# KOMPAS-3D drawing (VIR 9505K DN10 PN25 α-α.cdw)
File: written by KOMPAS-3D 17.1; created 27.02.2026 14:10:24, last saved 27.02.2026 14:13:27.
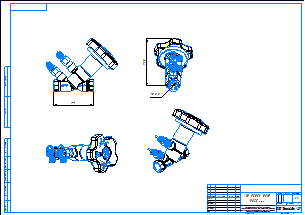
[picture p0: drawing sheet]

Sheet 1: A2, landscape

Title block, sheet 1: name: VIR 9505K DN10 / PN25 р-р; material: Внимание! Данный продукт является объектом авторского права ООО «Торговый Дом АДЛ». / Запрещается изменение, копирование, распространение / (в том числе путем копирования на другие сайты и ресурсы в Интернете) / или любое иное использование информации и объектов без предварительного / согласия правообладателя (ООО «Торговый Дом АДЛ»).; sheets: 1; organisation: ООО "Торговый дом АДЛ"; sheet format: A2

Views: Вид 1, Спереди, Проекционный вид 2, Проекционный вид 3, Вид 4, Изометрия
Referenced files in C:\Users\mipv\Desktop\VIR 9505K STP формат\: VIR 9505K DN10 PN25 р-р.m3d
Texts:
  adm
Dimensions and other numbers on the sheet: 92,5; 77; 1:1; 1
